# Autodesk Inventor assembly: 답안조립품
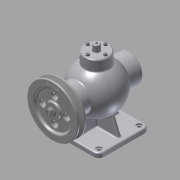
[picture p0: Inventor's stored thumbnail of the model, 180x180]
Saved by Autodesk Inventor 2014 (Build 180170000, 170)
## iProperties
Created: 2015-10
Part Number: 답안조립품
Document SubType Name: Assembly
Designer: youjin16
Author: youjin16
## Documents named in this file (19)
- C:\Users\youjin16\Desktop\451010V1002\답안조립품.iam
- C:\Users\youjin16\Desktop\451010V1002\본체.ipt
- C:\Users\youjin16\Desktop\451010V1002\앞커버.ipt
- C:\Users\youjin16\Desktop\451010V1002\뒤커버.ipt
- C:\Users\youjin16\Desktop\451010V1002\상부커버.ipt
- C:\Users\youjin16\Desktop\451010V1002\볼트 M4 x 16.ipt
- C:\Users\youjin16\Desktop\451010V1002\볼트 M 4 x 12.ipt
- C:\Users\youjin16\Desktop\451010V1002\오일실 15 30 7.ipt
- C:\Users\youjin16\Desktop\451010V1002\멈춤링- 15 x 1.ipt
- C:\Users\youjin16\Desktop\451010V1002\베어링- 6202.ipt
- KS B 2023 - 6202 - 15 x 35 x 11 - 7.8.ipt
- C:\Users\youjin16\Desktop\451010V1002\부시.ipt
- C:\Users\youjin16\Desktop\451010V1002\편심축.ipt
- C:\Users\youjin16\Desktop\451010V1002\멈춤링- 35x1.6.ipt
- KS B 1336 - 35x1.6.ipt
- C:\Users\youjin16\Desktop\451010V1002\슬라이드.ipt
- C:\Users\youjin16\Desktop\451010V1002\키 4 x 4 x 12.ipt
- C:\Users\youjin16\Desktop\451010V1002\V-벨트풀리.ipt
- C:\Users\youjin16\Desktop\451010V1002\너트 M8.ipt
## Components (16 placed, 5 different names)
1. KS B 2023 - 6202 - 15 x 35 x 11 - 7.8:1 — 각도:2
2. KS B 2023 - 6202 - 15 x 35 x 11 - 7.8:2 — 각도:1
3. KS B 1336 - 35x1.6:1
4. V-벨트풀리:1
5. KS B 1021 - 에 따름 ISO 1207 - 미터 A  M 4 x 12:1
6. KS B 1021 - 에 따름 ISO 1207 - 미터 A  M 4 x 12:2
7. KS B 1021 - 에 따름 ISO 1207 - 미터 A  M 4 x 12:3
8. KS B 1021 - 에 따름 ISO 1207 - 미터 A  M 4 x 12:4
9. ISO 4762 M4 x 16:2
10. ISO 4762 M4 x 16:3
11. ISO 4762 M4 x 16:4
12. ISO 4762 M4 x 16:5
13. ISO 4762 M4 x 16:1
14. ISO 4762 M4 x 16:6
15. ISO 4762 M4 x 16:7
16. ISO 4762 M4 x 16:8
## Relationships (2: Angle 2)
- 각도:1 [Angle]: KS B 2023 - 6202 - 15 x 35 x 11 - 7.8:2
- 각도:2 [Angle]: KS B 2023 - 6202 - 15 x 35 x 11 - 7.8:1
